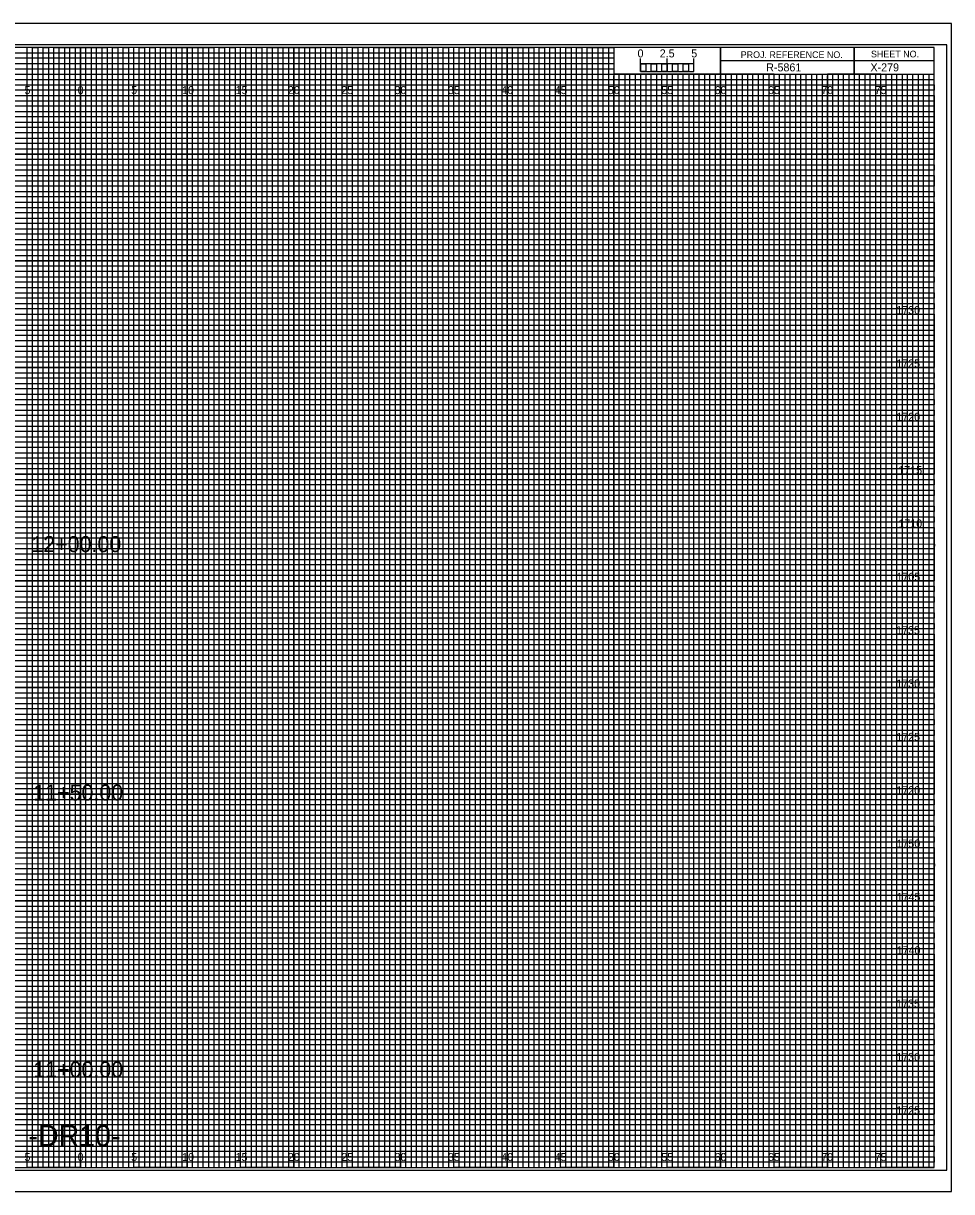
# Model space of a CAD drawing. Extents: x -7 to 162, y -2 to 107.
# Drawn here: x 74.6 to 161.7, y -2.3 to 107.3 of the extents above; entities that cross this region are included whole.
import ezdxf

# ---------------------------------------------------------------- set-up
doc = ezdxf.new("R2010")
doc.units = 0
for name, color, linetype in [('Prop XS Alignment Label', 7, 'Continuous'), ('Prop XS Bar Scale Labels', 7, 'Continuous'), ('Prop XS Elevation Labels', 7, 'Continuous'), ('Prop XS Offset Labels', 7, 'Continuous'), ('Prop XS Project Number', 7, 'Continuous'), ('Prop XS Sheet Number', 7, 'Continuous'), ('Prop XS Station Labels', 7, 'Continuous'), ('Sheet Cross Section CELL', 7, 'Continuous'), ('Sheet Cross Section Grid Major CELL', 7, 'Continuous'), ('Sheet Cross Section Grid Middle CELL', 7, 'Continuous'), ('Sheet Cross Section Grid Minor 1 CELL', 7, 'Continuous'), ('Sheet Cross Section Grid Minor 2 CELL', 7, 'Continuous'), ('Sheet Cross Section Scale CELL', 7, 'Continuous'), ('Sheet Cutting Line CELL', 7, 'Continuous'), ('Sheet DOT Grid CELL', 7, 'Continuous'), ('Sheet Plot Border Inside CELL', 7, 'Continuous'), ('Sheet Plot Border Outside CELL', 7, 'Continuous')]:
    doc.layers.add(name, color=color, linetype=linetype)

msp = doc.modelspace()

# ---------------------------------------------------------------- linework, layer by layer
at = {"layer": 'Sheet Cross Section CELL'}
for p, q in [((152.5, 105), (152.5, 102.5)), ((152.5, 102.5), (152.5, 105)), ((160, 103.75), (140, 103.75)), ((140, 103.75), (140, 102.5)), ((140, 102.5), (160, 102.5))]:
    msp.add_line(p, q, dxfattribs=at)
for points in [[(160, 105), (0, 105), (0, 0), (160, 0)], [(140, 105), (130, 105), (130, 102.52), (140, 102.52)], [(160, 105), (140, 105), (140, 102.5), (160, 102.5)]]:
    msp.add_lwpolyline(points, close=True, dxfattribs=at)
at = {"layer": 'Sheet Cross Section Grid Major CELL'}
for p, q in [((75, 105), (70, 105)), ((75, 0), (75, 105)), ((85, 105), (80, 105)), ((80, 105), (80, 0)), ((85, 0), (85, 105)), ((95, 105), (90, 105)), ((90, 105), (90, 0)), ((95, 0), (95, 105)), ((105, 105), (100, 105)), ((100, 105), (100, 0)), ((105, 0), (105, 105)), ((115, 105), (110, 105)), ((110, 105), (110, 0)), ((115, 0), (115, 105)), ((125, 105), (120, 105)), ((120, 105), (120, 0)), ((125, 0), (125, 105)), ((130, 105), (130, 0)), ((135, 0), (135, 102.5)), ((145, 102.5), (140, 102.5)), ((140, 102.5), (140, 0)), ((145, 0), (145, 102.5)), ((155, 102.5), (150, 102.5)), ((150, 102.5), (150, 0)), ((155, 0), (155, 102.5)), ((80, 0), (75, 0)), ((90, 0), (85, 0)), ((100, 0), (95, 0)), ((110, 0), (105, 0)), ((120, 0), (115, 0)), ((130, 0), (125, 0)), ((140, 0), (135, 0)), ((150, 0), (145, 0)), ((160, 0), (155, 0)), ((160, 0), (160, 0))]:
    msp.add_line(p, q, dxfattribs=at)
for points in [[(0, 100), (160, 100), (160, 95), (0, 95)], [(0, 90), (160, 90), (160, 85), (0, 85)], [(0, 80), (160, 80), (160, 75), (0, 75)], [(0, 70), (160, 70), (160, 65), (0, 65)], [(0, 60), (160, 60), (160, 55), (0, 55)], [(0, 50), (160, 50), (160, 45), (0, 45)], [(0, 40), (160, 40), (160, 35), (0, 35)], [(0, 30), (160, 30), (160, 25), (0, 25)], [(0, 20), (160, 20), (160, 15), (0, 15)], [(0, 10), (160, 10), (160, 5), (0, 5)]]:
    msp.add_lwpolyline(points, dxfattribs=at)
at = {"layer": 'Sheet Cross Section Grid Middle CELL'}
for points in [[(72.5, 0), (77.5, 0), (77.5, 105), (82.5, 105), (82.5, 0), (87.5, 0), (87.5, 105), (92.5, 105), (92.5, 0), (97.5, 0), (97.5, 105), (102.5, 105), (102.5, 0), (107.5, 0), (107.5, 105), (112.5, 105), (112.5, 0), (117.5, 0), (117.5, 105), (122.5, 105), (122.5, 0), (127.5, 0), (127.5, 105), (129.97, 105), (130, 105), (130, 102.5), (132.5, 102.5), (132.5, 0), (137.5, 0), (137.5, 102.5), (142.5, 102.5), (142.5, 0), (147.5, 0), (147.5, 102.5), (152.5, 102.5), (152.5, 0), (157.5, 0), (157.5, 102.5)], [(0, 102.5), (137.5, 102.5)], [(0, 92.5), (160, 92.5), (160, 97.5), (0, 97.5)], [(0, 82.5), (160, 82.5), (160, 87.5), (0, 87.5)], [(0, 72.5), (160, 72.5), (160, 77.5), (0, 77.5)], [(0, 62.5), (160, 62.5), (160, 67.5), (0, 67.5)], [(0, 52.5), (160, 52.5), (160, 57.5), (0, 57.5)], [(0, 42.5), (160, 42.5), (160, 47.5), (0, 47.5)], [(0, 32.5), (160, 32.5), (160, 37.5), (0, 37.5)], [(0, 22.5), (160, 22.5), (160, 27.5), (0, 27.5)], [(0, 12.5), (160, 12.5), (160, 17.5), (0, 17.5)], [(0, 2.5), (160, 2.5), (160, 7.5), (0, 7.5)]]:
    msp.add_lwpolyline(points, dxfattribs=at)
at = {"layer": 'Sheet Cross Section Grid Minor 1 CELL'}
for p, q in [((0, 104.5), (130, 104.5)), ((130, 104.5), (130, 103.99)), ((130, 103.99), (0, 103.99)), ((0, 103.5), (130, 103.5)), ((130, 102.95), (0, 102.95)), ((130, 103.5), (130, 102.95)), ((0, 102), (160, 102))]:
    msp.add_line(p, q, dxfattribs=at)
for points in [[(0, 101.5), (135, 101.5), (160, 101.5), (160, 101), (0, 101)], [(0, 100.5), (160, 100.5), (160, 99.5), (0, 99.5)], [(0, 99), (160, 99), (160, 98.5), (0, 98.49)], [(0, 98), (160, 98), (160, 97), (0, 97)], [(0, 96.5), (160, 96.5), (160, 96), (0, 96)], [(0, 95.5), (160, 95.5), (160, 94.5), (0, 94.5)], [(0, 94), (160, 94), (160, 93.5), (0, 93.5)], [(0, 93), (160, 93), (160, 92), (0, 92)], [(0, 91.5), (160, 91.5), (160, 91), (0, 91)], [(0, 90.5), (160, 90.5), (160, 89.5), (0, 89.5)], [(0, 89), (160, 89), (160, 88.5), (0, 88.5)], [(0, 88), (160, 88), (160, 86.98), (160, 86.5), (160, 86), (0, 86)], [(0, 87), (160, 87), (160, 86.5), (0, 86.5)], [(0, 85.5), (160, 85.5), (160, 84.5), (0, 84.52)], [(0, 84.52), (160, 84.5), (160, 84), (0, 84)], [(0, 83.5), (160, 83.5), (160, 83), (0, 83)], [(0, 82), (160, 82), (160, 81.5), (0, 81.5)], [(0, 81), (160, 81), (160, 80.5), (0, 80.5)], [(-0.04, 79.45), (160, 79.45), (160, 78.94), (-0.04, 78.94)], [(0, 78.5), (160, 78.5), (160, 78), (0, 78)], [(0, 77), (160, 77), (160, 76.5), (0, 76.5)], [(0, 76), (160, 76), (160, 75.5), (0, 75.5)], [(0, 74.5), (160, 74.5), (160, 74), (0, 74)], [(0, 73.5), (160, 73.5), (160, 73), (0, 73)], [(0, 72), (160, 72), (160, 71.5), (0, 71.5)], [(0, 71), (160, 71), (160, 70.5), (0, 70.5)], [(0, 69.5), (160, 69.5), (160, 68.99), (0, 69)], [(0, 68.5), (160, 68.5), (160, 68), (0, 68)], [(0, 67), (160, 67), (160, 66.5), (0, 66.5)], [(0, 66), (160, 66), (160, 65.5), (0, 65.5)], [(0, 64.5), (160, 64.5), (160, 64), (0, 64)], [(0, 63.5), (160, 63.5), (160, 63), (0, 63)], [(0, 62), (160, 62), (160, 61.5), (0, 61.5)], [(0, 61), (160, 61), (160, 60.5), (0, 60.5)], [(0, 59.5), (160, 59.5), (160, 59), (0, 59)], [(0, 58.5), (160.03, 58.45), (160, 58), (0, 58)], [(0, 57), (160, 57), (160, 56.5), (0, 56.5)], [(0, 56), (160, 56), (160, 55.5), (0, 55.5)], [(0, 54.5), (160, 54.5), (160, 54), (0, 54)], [(0, 53.5), (160, 53.5), (160, 53), (0, 53)], [(0, 52), (160, 52), (160, 51.5), (0, 51.5)], [(0, 51), (160, 51), (160, 50.5), (0, 50.5)], [(0, 49.5), (160, 49.5), (160, 49), (0, 49)], [(0, 48.5), (160, 48.5), (160, 48), (0, 48)], [(0, 47), (160, 47), (160, 46.5), (0, 46.5)], [(0, 46), (160, 46), (160, 45.5), (0, 45.5)], [(0, 44.5), (160, 44.5), (160, 44), (0, 44)], [(0, 43.5), (160, 43.5), (160, 43), (0, 43)], [(0, 42), (160, 42), (160, 41.5), (0, 41.5)], [(0, 41), (160, 41), (160, 40.5), (0, 40.5)], [(0, 39.5), (160, 39.5), (160, 38.99), (0, 39)], [(0, 38.5), (160, 38.5), (160, 38), (0, 38)], [(0, 37), (160, 37), (160, 36.5), (0, 36.5)], [(0, 36), (160, 36), (160, 35.5), (0, 35.5)], [(0, 34.5), (160, 34.5), (160, 34), (0, 34)], [(0, 33.5), (160, 33.5), (160, 33), (0, 33)], [(0, 32), (160, 32), (160, 31.5), (0, 31.5)], [(0, 31), (160, 31), (160, 30.5), (0, 30.5)], [(0, 29.5), (160, 29.5), (160, 29), (0, 29)], [(0, 28.5), (160.03, 28.46), (160, 28), (0, 28)], [(0, 27), (160, 27), (160, 26.5), (0, 26.5)], [(0, 26), (160, 26), (160, 25.5), (0, 25.5)], [(0, 24.5), (160, 24.5), (160, 24), (0, 24)], [(0, 23.5), (160, 23.5), (160, 23), (0, 23)], [(0, 22), (160, 22), (160, 21.5), (0, 21.5)], [(0, 21), (160, 21), (160, 20.5), (0, 20.5)], [(0, 19.5), (160, 19.5), (160, 19), (0, 19)], [(0, 18.5), (160, 18.5), (160, 18), (0, 18)], [(0, 17), (160, 17), (160, 16.5), (0, 16.5)], [(0, 16), (160, 16), (160, 15.5), (0, 15.5)], [(0, 14.5), (160, 14.5), (160, 14), (0, 14)], [(0, 13.5), (160, 13.5), (160, 13), (0, 13)], [(0, 12), (160, 12), (160, 11.5), (0, 11.5)], [(0, 11), (160, 11), (160, 10.5), (0, 10.5)], [(0, 9.5), (160, 9.5), (160, 9), (0, 9)], [(0, 8.5), (160, 8.5), (160, 8), (0, 8)], [(0, 7), (160, 7), (160, 6.5), (0, 6.5)], [(0, 6), (160, 6), (160, 5.5), (0, 5.5)], [(0, 4.5), (160, 4.5), (160, 4), (0, 4)], [(0, 3.5), (160, 3.5), (160, 3), (0, 3)], [(0, 2), (160, 2), (160, 1.5), (0, 1.5)], [(0, 1), (160, 1), (160, 0.5), (0, 0.5)]]:
    msp.add_lwpolyline(points, dxfattribs=at)
at = {"layer": 'Sheet Cross Section Grid Minor 2 CELL'}
for p, q in [((133.5, 102.5), (133, 102.5)), ((133, 102.5), (133, 0)), ((133.5, 0), (133.5, 102.5)), ((134.5, 102.5), (134, 102.5)), ((134, 102.5), (134, 0)), ((134.5, 0), (134.5, 102.5)), ((133, 0), (132.5, 0)), ((134, 0), (133.5, 0))]:
    msp.add_line(p, q, dxfattribs=at)
for points in [[(75, 0), (75.5, 0), (75.5, 105), (76, 105), (76, 0)], [(76, 0), (76.5, 0), (76.5, 105), (77, 105), (77, 0)], [(77.5, 0), (78, 0), (78, 105), (78.5, 105), (78.5, 0)], [(78.5, 0), (79, 0), (79, 105), (79.5, 105), (79.5, 0)], [(80, 0), (80.5, 0), (80.5, 105), (81, 105), (81, 0)], [(81, 0), (81.5, 0), (81.5, 105), (82, 105), (82, 0)], [(82.5, 0), (83, 0), (83, 105), (83.5, 105), (83.5, 0)], [(83.5, 0), (84, 0), (84, 105), (84.5, 105), (84.5, 0)], [(85, 0), (85.5, 0), (85.5, 105), (86, 105), (86, 0)], [(86, 0), (86.5, 0), (86.5, 105), (87, 105), (87, 0)], [(87.5, 0), (88, 0), (88, 105), (88.5, 105), (88.5, 0)], [(88.5, 0), (89, 0), (89, 105), (89.5, 105), (89.5, 0)], [(90, 0), (90.5, 0), (90.5, 105), (91, 105), (91, 0)], [(91, 0), (91.5, 0), (91.5, 105), (92, 105), (92, 0)], [(92.5, 0), (93, 0), (93, 105), (93.5, 105), (93.5, 0)], [(93.5, 0), (94, 0), (94, 105), (94.5, 105), (94.5, 0)], [(95, 0), (95.5, 0), (95.5, 105), (96, 105), (96, 0)], [(96, 0), (96.5, 0), (96.5, 105), (97, 105), (97, 0)], [(97.5, 0), (98, 0), (98, 105), (98.5, 105), (98.5, 0)], [(98.5, 0), (99, 0), (99, 105), (99.5, 105), (99.5, 0)], [(100, 0), (100.5, 0), (100.5, 105), (101, 105), (101, 0)], [(101, 0), (101.5, 0), (101.5, 105), (102, 105), (102, 0)], [(102.5, 0), (103, 0), (103, 105), (103.5, 105), (103.5, 0)], [(103.5, 0), (104, 0), (104, 105), (104.5, 105), (104.5, 0)], [(105, 0), (105.5, 0), (105.5, 105), (106, 105), (106, 0)], [(106, 0), (106.5, 0), (106.5, 105), (107, 105), (107, 0)], [(107.5, 0), (108, 0), (108, 105), (108.5, 105), (108.5, 0)], [(108.5, 0), (109, 0), (109, 105), (109.5, 105), (109.5, 0)], [(110, 0), (110.5, 0), (110.5, 105), (111, 105), (111, 0)], [(111, 0), (111.5, 0), (111.5, 105), (112, 105), (112, 0)], [(112.5, 0), (113, 0), (113, 105), (113.5, 105), (113.5, 0)], [(113.5, 0), (114, 0), (114, 105), (114.5, 105), (114.5, 0)], [(115, 0), (115.5, 0), (115.5, 105), (116, 105), (116, 0)], [(116, 0), (116.5, 0), (116.5, 105), (117, 105), (117, 0)], [(117.5, 0), (118, 0), (118, 105), (118.5, 105), (118.5, 0)], [(118.5, 0), (119, 0), (119, 105), (119.5, 105), (119.5, 0)], [(120, 0), (120.5, 0), (120.5, 105), (121, 105), (121, 0)], [(121, 0), (121.5, 0), (121.5, 105), (122, 105), (122, 0)], [(122.5, 0), (123, 0), (123, 105), (123.5, 105), (123.5, 0)], [(123.5, 0), (124, 0), (124, 105), (124.5, 105), (124.5, 0)], [(125, 0), (125.5, 0), (125.5, 105), (126, 105), (126, 0)], [(126, 0), (126.5, 0), (126.5, 105), (127, 105), (127, 0)], [(127.5, 0), (128, 0), (128, 105), (128.5, 105), (128.5, 0)], [(128.5, 0), (129, 0), (129, 105), (129.5, 105), (129.5, 0)], [(130, 0), (130.5, 0), (130.5, 102.5), (131.01, 102.5), (131.01, 0)], [(131, 0), (131.5, 0), (131.5, 102.5), (132, 102.5), (132, 0)], [(135, 0), (135.49, 0), (135.49, 102.5), (136, 102.5), (136, 0)], [(136, 0), (136.5, 0), (136.5, 102.5), (137.03, 102.5), (137.03, 0)], [(137.5, 0), (138, 0), (138, 102.5), (138.5, 102.5), (138.5, 0)], [(138.5, 0), (139, 0), (139, 102.5), (139.5, 102.5), (139.5, 0)], [(140, 0), (140.5, 0), (140.5, 102.5), (141, 102.5), (141, 0)], [(141, 0), (141.5, 0), (141.5, 102.5), (142, 102.5), (142, 0)], [(142.5, 0), (143, 0), (143, 102.5), (143.5, 102.5), (143.5, 0)], [(143.5, 0), (144, 0), (144, 102.5), (144.5, 102.5), (144.5, 0)], [(145, 0), (145.5, 0), (145.5, 102.5), (146, 102.5), (146, 0)], [(146, 0), (146.5, 0), (146.5, 102.5), (147, 102.5), (147, 0)], [(147.5, 0), (148, 0), (148, 102.5), (148.5, 102.5), (148.5, 0)], [(148.5, 0), (149, 0), (149, 102.5), (149.5, 102.5), (149.5, 0)], [(150, 0), (150.5, 0), (150.5, 102.5), (151, 102.5), (151, 0)], [(151, 0), (151.5, 0), (151.5, 102.5), (152, 102.5), (152, 0)], [(152.5, 0), (153, 0), (153, 102.5), (153.5, 102.5), (153.5, 0)], [(153.5, 0), (154, 0), (154, 102.5), (154.5, 102.5), (154.5, 0)], [(155, 0), (155.5, 0), (155.5, 102.5), (156, 102.5), (156, 0)], [(156, 0), (156.5, 0), (156.5, 102.5), (157, 102.5), (157, 0)], [(157.5, 0), (158, 0), (158, 102.5), (158.5, 102.5), (158.5, 0)], [(158.5, 0), (159, 0), (159, 102.5), (159.5, 102.5), (159.5, 0)]]:
    msp.add_lwpolyline(points, dxfattribs=at)
at = {"layer": 'Sheet Cross Section Scale CELL'}
for p, q in [((132.5, 102.75), (132.5, 103.95)), ((132.5, 103.45), (132.5, 103.95)), ((135, 102.75), (135, 103.95)), ((137.5, 102.75), (137.5, 103.95)), ((137.5, 103.45), (137.5, 103.95))]:
    msp.add_line(p, q, dxfattribs=at)
for points in [[(137.5, 103.45), (132.5, 103.45), (132.5, 102.75), (137.5, 102.75)], [(132.5, 103.45), (133, 103.45), (133, 102.75), (132.5, 102.75)], [(133.5, 103.45), (134, 103.45), (134, 102.75), (133.5, 102.75)], [(134.5, 103.45), (135, 103.45), (135, 102.75), (134.5, 102.75)], [(135.5, 103.45), (136, 103.45), (136, 102.75), (135.5, 102.75)], [(136.5, 103.45), (137, 103.45), (137, 102.75), (136.5, 102.75)]]:
    msp.add_lwpolyline(points, close=True, dxfattribs=at)
at = {"layer": 'Sheet Cutting Line CELL'}
for p, q in [((161.65, 107.25), (-6.7, 107.25)), ((-6.7, -2.25), (161.65, -2.25))]:
    msp.add_line(p, q, dxfattribs=at)
at = {"layer": 'Sheet DOT Grid CELL'}
for p, q in [((75, 0), (75, 105)), ((80, 0), (80, 105)), ((85, 0), (85, 105)), ((90, 0), (90, 105)), ((95, 0), (95, 105)), ((100, 0), (100, 105)), ((105, 0), (105, 105)), ((110, 0), (110, 105)), ((115, 0), (115, 105)), ((120, 0), (120, 105)), ((125, 0), (125, 105)), ((130, 0), (130, 102.34)), ((135, 0), (135, 102.34)), ((140, 0), (140, 102.34)), ((145, 0), (145, 102.34)), ((150, 0), (150, 102.34)), ((155, 0), (155, 102.34)), ((0, 100), (160, 100)), ((0, 95), (160, 95)), ((0, 90), (160, 90)), ((0, 85), (160, 85)), ((0, 80), (160, 80)), ((0, 75), (160, 75)), ((0, 70), (160, 70)), ((0, 65), (160, 65)), ((0, 60), (160, 60)), ((0, 55), (160, 55)), ((0, 50), (160, 50)), ((0, 45), (160, 45)), ((0, 40), (160, 40)), ((0, 35), (160, 35)), ((0, 30), (160, 30)), ((0, 25), (160, 25)), ((0, 20), (160, 20)), ((0, 15), (160, 15)), ((0, 10), (160, 10)), ((0, 5), (160, 5))]:
    msp.add_line(p, q, dxfattribs=at)
at = {"layer": 'Sheet Plot Border Inside CELL'}
msp.add_lwpolyline([(-5.4, -0.25), (161.2, -0.25), (161.2, 105.25), (-5.4, 105.25)], close=True, dxfattribs=at)
at = {"layer": 'Sheet Plot Border Outside CELL'}
msp.add_lwpolyline([(-6.7, -2.25), (161.65, -2.25), (161.65, 107.25), (-6.7, 107.25)], close=True, dxfattribs=at)

# ---------------------------------------------------------------- texts
at = {"layer": 'Prop XS Alignment Label'}
msp.add_text('-DR10-', height=2, dxfattribs=at).set_placement((75.12, 2))
at = {"layer": 'Prop XS Bar Scale Labels'}
for s, p in [('2.5', (134.29, 104.06)), ('5', (137.24, 104.06))]:
    msp.add_text(s, height=0.75, dxfattribs=at).set_placement(p)
at = {"layer": 'Prop XS Elevation Labels'}
for s, p in [('1730', (156.46, 80)), ('1725', (156.46, 75)), ('1720', (156.47, 70)), ('1715', (156.65, 65)), ('1710', (156.66, 60)), ('1705', (156.48, 55)), ('1735', (156.45, 50)), ('1730', (156.46, 45)), ('1725', (156.46, 40)), ('1720', (156.47, 35)), ('1750', (156.48, 30)), ('1745', (156.49, 25)), ('1740', (156.5, 20)), ('1735', (156.45, 15)), ('1730', (156.46, 10)), ('1725', (156.46, 5))]:
    msp.add_text(s, height=0.75, dxfattribs=at).set_placement(p)
at = {"layer": 'Prop XS Offset Labels'}
for s, p in [('5', (74.74, 100.62)), ('0', (79.73, 100.62)), ('0', (79.73, 100.62)), ('5', (84.74, 100.62)), ('10', (89.52, 100.62)), ('15', (94.53, 100.62)), ('20', (99.43, 100.62)), ('25', (104.44, 100.62)), ('30', (109.43, 100.62)), ('35', (114.44, 100.62)), ('40', (119.43, 100.62)), ('45', (124.44, 100.62)), ('50', (129.43, 100.62)), ('55', (134.44, 100.62)), ('60', (139.43, 100.62)), ('65', (144.44, 100.62)), ('70', (149.43, 100.62)), ('75', (154.44, 100.62)), ('5', (74.74, 0.62)), ('0', (79.73, 0.62)), ('0', (79.73, 0.62)), ('5', (84.74, 0.62)), ('10', (89.52, 0.62)), ('15', (94.53, 0.62)), ('20', (99.43, 0.62)), ('25', (104.44, 0.62)), ('30', (109.43, 0.62)), ('35', (114.44, 0.62)), ('40', (119.43, 0.62)), ('45', (124.44, 0.62)), ('50', (129.43, 0.62)), ('55', (134.44, 0.62)), ('60', (139.43, 0.62)), ('65', (144.44, 0.62)), ('70', (149.43, 0.62)), ('75', (154.44, 0.62))]:
    msp.add_text(s, height=0.75, dxfattribs=at).set_placement(p)
at = {"layer": 'Prop XS Project Number'}
msp.add_text('R-5861', height=0.75, dxfattribs=at).set_placement((144.27, 102.75))
at = {"layer": 'Prop XS Sheet Number'}
msp.add_text('X-279', height=0.75, dxfattribs=at).set_placement((154.04, 102.75))
at = {"layer": 'Prop XS Station Labels'}
for s, p in [('12+00.00', (75.39, 57.69)), ('11+50.00', (75.57, 34.41)), ('11+00.00', (75.57, 8.45))]:
    msp.add_text(s, height=1.5, dxfattribs=at).set_placement(p)
at = {"layer": 'Sheet Cross Section CELL'}
for s, p in [('PROJ. REFERENCE NO.', (141.88, 104)), ('SHEET NO.', (154.09, 104.06))]:
    msp.add_text(s, height=0.625, dxfattribs=at).set_placement(p)
at = {"layer": 'Sheet Cross Section Scale CELL'}
msp.add_text('0', height=0.75, dxfattribs=at).set_placement((132.21, 104.06))

doc.saveas('drawing.dxf')
